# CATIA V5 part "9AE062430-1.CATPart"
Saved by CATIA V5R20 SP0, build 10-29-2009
Part number: 9AE062430-1
Revision: ANY
Definition: UNKNOWN
Nomenclature: 9AE062430-1
Source: Unknown
Bounding box of the stored display mesh (mm): x -8 to 8, y 0 to 76.999, z -8 to 8
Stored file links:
  C:\Users\Utente\Desktop\IO LAVORO\3D X SITO CF\CUMSA\3D files AE\AE 062430\9AE062430-1.CATPart
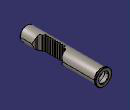
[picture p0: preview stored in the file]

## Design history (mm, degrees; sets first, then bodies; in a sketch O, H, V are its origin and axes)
Body1 "Chaflán2" (main body)
  Solid1: solid without history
